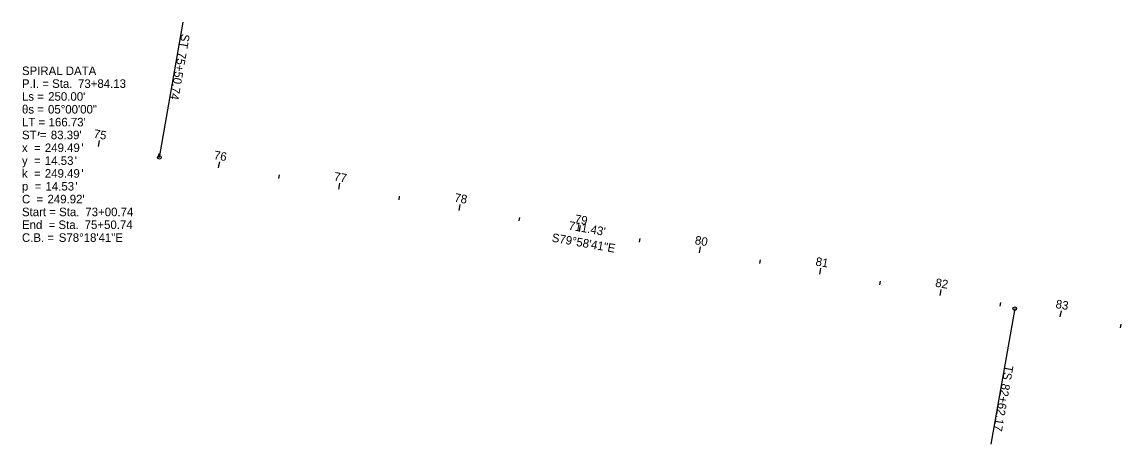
# Model space of a CAD drawing. Extents: x 1999328 to 2003366, y 252318 to 253988.
# Drawn here: x 2000155 to 2001055, y 253219 to 253564 of the extents above; entities that cross this region are included whole.
import ezdxf

# ---------------------------------------------------------------- set-up
doc = ezdxf.new("R2010")
doc.units = 0
for name, color, linetype in [('GE_P_Alignment_500_Stations', 7, 'Continuous'), ('GE_X_Alignment_100_Stations', 7, 'Continuous'), ('SC_Scratch3', 7, 'Continuous'), ('SV_X_Mon_Cells_Found', 7, 'Continuous'), ('TX_P_50', 7, 'Continuous'), ('TX_X_50', 7, 'Continuous')]:
    doc.layers.add(name, color=color, linetype=linetype)

msp = doc.modelspace()

# ---------------------------------------------------------------- linework, layer by layer
at = {"layer": 'GE_P_Alignment_500_Stations'}
for p, q in [((2000267.25, 253453.17), (2000286.83, 253563.95)), ((2000168.14, 253471.17), (2000168.7, 253474.12)), ((2000217.3, 253462.06), (2000218.19, 253466.98)), ((2000266.53, 253453.3), (2000267.05, 253456.25)), ((2000315.76, 253444.6), (2000316.63, 253449.52)), ((2000365, 253435.9), (2000365.52, 253438.85)), ((2000414.24, 253427.2), (2000415.11, 253432.12)), ((2000463.47, 253418.49), (2000464, 253421.45)), ((2000512.71, 253409.79), (2000513.58, 253414.72)), ((2000561.95, 253401.09), (2000562.47, 253404.05)), ((2000611.19, 253392.39), (2000612.06, 253397.31)), ((2000660.42, 253383.69), (2000660.95, 253386.64)), ((2000709.66, 253374.99), (2000710.53, 253379.91)), ((2000758.9, 253366.29), (2000759.42, 253369.24)), ((2000808.13, 253357.59), (2000809, 253362.51)), ((2000857.37, 253348.88), (2000857.89, 253351.84)), ((2000906.61, 253340.18), (2000907.48, 253345.11)), ((2000955.85, 253331.48), (2000956.37, 253334.44)), ((2000967.83, 253329.36), (2000948.25, 253218.58)), ((2001005.08, 253322.76), (2001005.96, 253327.68)), ((2001054.26, 253313.77), (2001054.82, 253316.72))]:
    msp.add_line(p, q, dxfattribs=at)
for centre in [(2000267.25, 253453.17), (2000967.83, 253329.36)]:
    msp.add_circle(centre, 1.5, dxfattribs=at)
at = {"layer": 'SV_X_Mon_Cells_Found'}
for p, q in [((2000267.25, 253453.17), (2000286.83, 253563.95)), ((2000217.3, 253462.06), (2000217.83, 253465.01)), ((2000709.66, 253374.99), (2000710.53, 253379.91)), ((2000967.83, 253329.36), (2000948.25, 253218.58))]:
    msp.add_line(p, q, dxfattribs=at)
for centre in [(2000267.25, 253453.17), (2000967.83, 253329.36)]:
    msp.add_circle(centre, 1.5, dxfattribs=at)
at = {"layer": 'TX_P_50'}
for p, q in [((2000267.25, 253453.17), (2000286.83, 253563.95)), ((2000217.3, 253462.06), (2000218.19, 253466.98)), ((2000315.76, 253444.6), (2000316.29, 253447.55)), ((2000414.24, 253427.2), (2000414.76, 253430.15)), ((2000512.71, 253409.79), (2000513.23, 253412.75)), ((2000611.19, 253392.39), (2000611.71, 253395.34)), ((2000709.66, 253374.99), (2000710.53, 253379.91)), ((2000808.13, 253357.59), (2000808.66, 253360.54)), ((2000906.61, 253340.18), (2000907.13, 253343.14)), ((2000967.83, 253329.36), (2000948.25, 253218.58)), ((2001005.08, 253322.76), (2001005.61, 253325.71))]:
    msp.add_line(p, q, dxfattribs=at)
for centre in [(2000267.25, 253453.17), (2000967.83, 253329.36)]:
    msp.add_circle(centre, 1.5, dxfattribs=at)

# ---------------------------------------------------------------- texts
at = {"layer": 'GE_P_Alignment_500_Stations'}
for s, rotation, p in [('ST', 259.97809, (2000285.31, 253554.65)), ('75+50.74', 259.97809, (2000282.66, 253539.66)), ('75', 349.77215, (2000213, 253469.31)), ('76', 349.97809, (2000311.46, 253451.82)), ('77', 349.97809, (2000409.78, 253434.33)), ('78', 349.97809, (2000508.43, 253417.02)), ('79', 349.97809, (2000606.96, 253399.6)), ("711.43'", 349.97809, (2000601.95, 253394.14)), ('S79°58\'41"E', 349.97809, (2000588.19, 253384.27)), ('80', 349.97809, (2000705.37, 253382.21)), ('81', 349.97809, (2000804.26, 253364.74)), ('82', 349.97809, (2000902.33, 253347.4)), ('83', 349.86359, (2001000.84, 253329.98)), ('TS', 259.97809, (2000959.82, 253283.38)), ('82+62.17', 259.97809, (2000957.17, 253268.39))]:
    msp.add_text(s, height=7, rotation=rotation, dxfattribs=at).set_placement(p)
at = {"layer": 'GE_X_Alignment_100_Stations'}
for s, p in [('SPIRAL DATA', (2000154.66, 253520.52)), ('P.I. = Sta. ', (2000154.66, 253510.02)), ('73+84.13', (2000200.58, 253510.02)), ('Ls = ', (2000154.66, 253499.52)), ("250.00'", (2000176.13, 253499.52)), ('θs = ', (2000154.66, 253489.02)), ('05°00\'00"', (2000176, 253489.02)), ('LT = ', (2000154.66, 253478.52)), ("166.73'", (2000176.49, 253478.52)), ('ST = ', (2000154.66, 253468.02)), ("83.39'", (2000178.3, 253468.02)), ('x  = ', (2000154.66, 253457.52)), ('249.49', (2000173.41, 253457.52)), ("'", (2000203.31, 253457.52)), ('y  = ', (2000154.66, 253447.02)), ('14.53', (2000173.41, 253447.02)), ("'", (2000197.87, 253447.02)), ('k  = ', (2000154.66, 253436.52)), ('249.49', (2000173.41, 253436.52)), ("'", (2000203.31, 253436.52)), ('14.53', (2000173.95, 253426.02)), ("'", (2000198.42, 253426.02)), ('p  = ', (2000154.66, 253426.02)), ('C  = ', (2000154.66, 253415.52)), ("249.92'", (2000175.58, 253415.52)), ('Start = Sta. ', (2000154.66, 253405.02)), ('73+00.74', (2000206.56, 253405.02)), ('End  = Sta. ', (2000154.66, 253394.52)), ('75+50.74', (2000206.02, 253394.52)), ('C.B. = ', (2000154.66, 253384.02)), ('S78°18\'41"E', (2000184.82, 253384.02))]:
    msp.add_text(s, height=7, dxfattribs=at).set_placement(p)
at = {"layer": 'SC_Scratch3'}
for s, p in [('SPIRAL DATA', (2000154.66, 253520.52)), ('P.I. = Sta. ', (2000154.66, 253510.02)), ('73+84.13', (2000200.58, 253510.02)), ('Ls = ', (2000154.66, 253499.52)), ("250.00'", (2000176.13, 253499.52)), ('θs = ', (2000154.66, 253489.02)), ('05°00\'00"', (2000176, 253489.02)), ('LT = ', (2000154.66, 253478.52)), ("166.73'", (2000176.49, 253478.52)), ('ST = ', (2000154.66, 253468.02)), ("83.39'", (2000178.3, 253468.02)), ('x  = ', (2000154.66, 253457.52)), ('249.49', (2000173.41, 253457.52)), ("'", (2000203.31, 253457.52)), ('y  = ', (2000154.66, 253447.02)), ('14.53', (2000173.41, 253447.02)), ("'", (2000197.87, 253447.02)), ('k  = ', (2000154.66, 253436.52)), ('249.49', (2000173.41, 253436.52)), ("'", (2000203.31, 253436.52)), ('14.53', (2000173.95, 253426.02)), ("'", (2000198.42, 253426.02)), ('p  = ', (2000154.66, 253426.02)), ('C  = ', (2000154.66, 253415.52)), ("249.92'", (2000175.58, 253415.52)), ('Start = Sta. ', (2000154.66, 253405.02)), ('73+00.74', (2000206.56, 253405.02)), ('End  = Sta. ', (2000154.66, 253394.52)), ('75+50.74', (2000206.02, 253394.52)), ('C.B. = ', (2000154.66, 253384.02)), ('S78°18\'41"E', (2000184.82, 253384.02))]:
    msp.add_text(s, height=7, dxfattribs=at).set_placement(p)
at = {"layer": 'SV_X_Mon_Cells_Found'}
for s, rotation, p in [('ST', 259.97809, (2000285.31, 253554.65)), ('75+50.74', 259.97809, (2000282.66, 253539.66)), ("711.43'", 349.97809, (2000601.95, 253394.14)), ('S79°58\'41"E', 349.97809, (2000588.19, 253384.27)), ('80', 349.97809, (2000705.37, 253382.21)), ('TS', 259.97809, (2000959.82, 253283.38)), ('82+62.17', 259.97809, (2000957.17, 253268.39))]:
    msp.add_text(s, height=7, rotation=rotation, dxfattribs=at).set_placement(p)
at = {"layer": 'TX_P_50'}
for s, rotation, p in [('ST', 259.97809, (2000285.31, 253554.65)), ('75+50.74', 259.97809, (2000282.66, 253539.66)), ('75', 349.77215, (2000213, 253469.31)), ("711.43'", 349.97809, (2000601.95, 253394.14)), ('S79°58\'41"E', 349.97809, (2000588.19, 253384.27)), ('80', 349.97809, (2000705.37, 253382.21)), ('TS', 259.97809, (2000959.82, 253283.38)), ('82+62.17', 259.97809, (2000957.17, 253268.39))]:
    msp.add_text(s, height=7, rotation=rotation, dxfattribs=at).set_placement(p)
at = {"layer": 'TX_X_50'}
for s, p in [('SPIRAL DATA', (2000154.66, 253520.52)), ('P.I. = Sta. ', (2000154.66, 253510.02)), ('73+84.13', (2000200.58, 253510.02)), ('Ls = ', (2000154.66, 253499.52)), ("250.00'", (2000176.13, 253499.52)), ('θs = ', (2000154.66, 253489.02)), ('05°00\'00"', (2000176, 253489.02)), ('LT = ', (2000154.66, 253478.52)), ("166.73'", (2000176.49, 253478.52)), ('ST = ', (2000154.66, 253468.02)), ("83.39'", (2000178.3, 253468.02)), ('x  = ', (2000154.66, 253457.52)), ('249.49', (2000173.41, 253457.52)), ("'", (2000203.31, 253457.52)), ('y  = ', (2000154.66, 253447.02)), ('14.53', (2000173.41, 253447.02)), ("'", (2000197.87, 253447.02)), ('k  = ', (2000154.66, 253436.52)), ('249.49', (2000173.41, 253436.52)), ("'", (2000203.31, 253436.52)), ('14.53', (2000173.95, 253426.02)), ("'", (2000198.42, 253426.02)), ('p  = ', (2000154.66, 253426.02)), ('C  = ', (2000154.66, 253415.52)), ("249.92'", (2000175.58, 253415.52)), ('Start = Sta. ', (2000154.66, 253405.02)), ('73+00.74', (2000206.56, 253405.02)), ('End  = Sta. ', (2000154.66, 253394.52)), ('75+50.74', (2000206.02, 253394.52)), ('C.B. = ', (2000154.66, 253384.02)), ('S78°18\'41"E', (2000184.82, 253384.02))]:
    msp.add_text(s, height=7, dxfattribs=at).set_placement(p)

doc.saveas('drawing.dxf')
